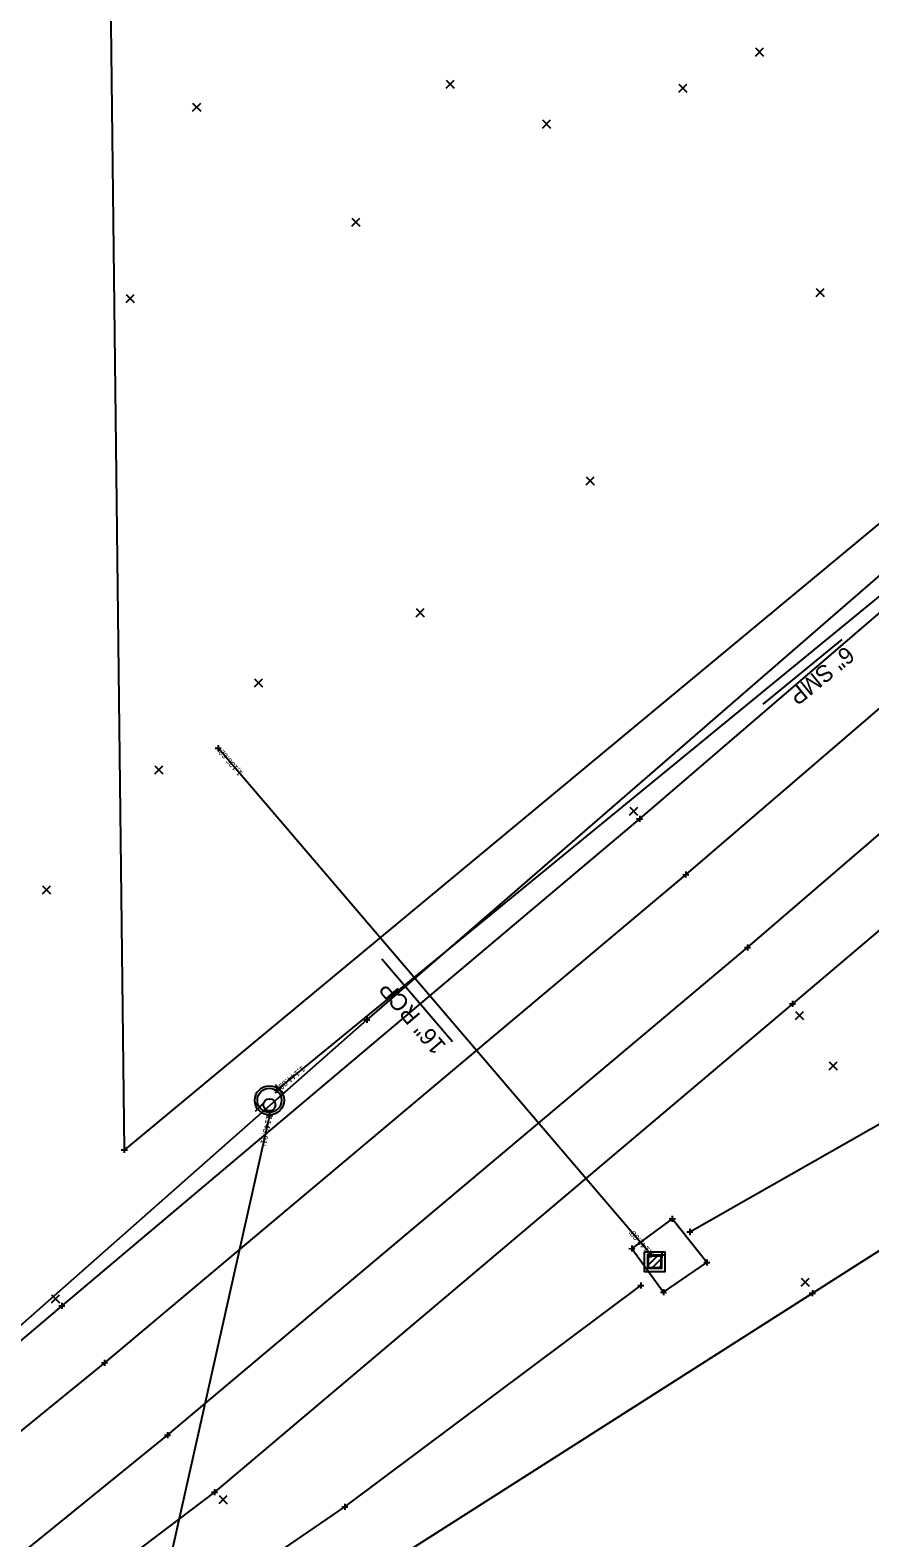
# Model space of a CAD drawing. Extents: x 142461 to 147261, y 511126 to 514697.
# Drawn here: x 145010.2 to 145149.5, y 513373.9 to 513623.9 of the extents above; entities that cross this region are included whole.
import ezdxf

# ---------------------------------------------------------------- set-up
doc = ezdxf.new("R2010")
doc.units = 0
for name, color, linetype in [('DR_X_Cells', 7, 'Continuous'), ('DR_X_Elev_Flow', 7, 'Continuous'), ('DR_X_Storm_Sewer', 7, 'Continuous'), ('DR_X_Text', 7, 'Continuous'), ('GK_Drainage_Nodes', 7, 'Continuous'), ('PM_X_Surveyed_Line', 7, 'Continuous'), ('PV_X_EOP', 7, 'Continuous'), ('RD_X_Concrete_Pad', 7, 'Continuous'), ('SC_Scratch1', 7, 'Continuous'), ('SV_X_Original_Ground', 7, 'Continuous'), ('SV_X_Random_Point', 7, 'Continuous'), ('SV_X_Shot_Marker', 7, 'Continuous'), ('SV_X_Toe_of_Slope', 7, 'Continuous'), ('SV_X_Top_of_Bank', 7, 'Continuous'), ('UT_X_Sanitary_Line', 7, 'Continuous'), ('VG_X_Tree_Line_Lt', 7, 'Continuous')]:
    doc.layers.add(name, color=color, linetype=linetype)

msp = doc.modelspace()

# ---------------------------------------------------------------- linework, layer by layer
at = {"layer": 'DR_X_Cells'}
for p, q in [((145112.65, 513419.06), (145114.41, 513420.82)), ((145112.65, 513420.19), (145113.28, 513420.82)), ((145113.25, 513418.53), (145114.94, 513420.22)), ((145114.38, 513418.53), (145114.94, 513419.09))]:
    msp.add_line(p, q, dxfattribs=at)
for points in [[(145112.13, 513421.34), (145115.46, 513421.34), (145115.46, 513418), (145112.13, 513418)], [(145112.65, 513420.82), (145114.94, 513420.82), (145114.94, 513418.53), (145112.65, 513418.53)], [(145112.8, 513420.67), (145114.8, 513420.67), (145114.8, 513418.67), (145112.8, 513418.67)]]:
    msp.add_lwpolyline(points, close=True, dxfattribs=at)
for centre, radius in [((145049.91, 513446.44), 2.42), ((145049.91, 513446.44), 2), ((145049.91, 513445.69), 1)]:
    msp.add_circle(centre, radius, dxfattribs=at)
at = {"layer": 'DR_X_Elev_Flow'}
for p, q in [((145050.66, 513448.16), (145051.66, 513448.16)), ((145051.16, 513448.66), (145051.16, 513447.66)), ((145051.16, 513448.16), (145051.16, 513448.16)), ((145049.45, 513443.91), (145050.45, 513443.91)), ((145049.95, 513444.41), (145049.95, 513443.41)), ((145049.95, 513443.91), (145049.95, 513443.91)), ((145115.01, 513421.35), (145115.01, 513420.35)), ((145114.51, 513420.85), (145115.51, 513420.85)), ((145115.01, 513420.85), (145115.01, 513420.85))]:
    msp.add_line(p, q, dxfattribs=at)
at = {"layer": 'DR_X_Storm_Sewer'}
msp.add_line((145113.14, 513420.9), (145041.41, 513504.82), dxfattribs=at)
at = {"layer": 'DR_X_Text'}
for p, q in [((145131.82, 513512.14), (145144.87, 513522.84)), ((145068.54, 513469.9), (145080.26, 513456.18))]:
    msp.add_line(p, q, dxfattribs=at)
at = {"layer": 'GK_Drainage_Nodes'}
for p, q in [((145049.91, 513448.44), (145049.91, 513448.44)), ((145049.91, 513446.44), (145049.91, 513446.44)), ((145049.91, 513446.44), (145049.91, 513446.44)), ((145049.91, 513445.69), (145049.91, 513445.69)), ((145049.91, 513444.44), (145049.91, 513444.44)), ((145113.8, 513421.34), (145113.8, 513421.34)), ((145112.8, 513419.67), (145112.8, 513419.67)), ((145113.8, 513420.67), (145113.8, 513420.67)), ((145113.8, 513419.67), (145113.8, 513419.67)), ((145113.8, 513419.67), (145113.8, 513419.67)), ((145113.8, 513419.67), (145113.8, 513419.67)), ((145114.8, 513419.67), (145114.8, 513419.67)), ((145113.8, 513418.67), (145113.8, 513418.67)), ((145113.8, 513418), (145113.8, 513418))]:
    msp.add_line(p, q, dxfattribs=at)
msp.add_circle((145049.91, 513446.44), 2, dxfattribs=at)
at = {"layer": 'PM_X_Surveyed_Line'}
for points in [[(145244.8, 513598.91), (145189.1, 513544.15), (145118.95, 513483.86), (145022.54, 513402.94), (144981.98, 513369.93), (144853.86, 513268.93), (144843.13, 513260.73), (144805.16, 513232.38), (144766.25, 513204.67), (144725.33, 513176.3), (144684.91, 513148.47), (144644.29, 513120.74), (144603.48, 513093.63), (144562.1, 513066.23), (144520.96, 513039), (144479.14, 513010.91), (144437.33, 512982.92), (144395.18, 512954.5), (144353.44, 512926.48), (144318.54, 512903.34), (144276.1, 512875.34), (144232.02, 512845.98), (144188.92, 512817.39), (144145.08, 512788.07)], [(144863.53, 513255.94), (144992.11, 513357.76), (145033.02, 513390.91), (145129.2, 513471.78), (145199.04, 513531.8), (145259.33, 513584.12)]]:
    msp.add_lwpolyline(points, dxfattribs=at)
at = {"layer": 'PV_X_EOP'}
for p, q in [((145181.78, 513553.71), (145111.31, 513493.11)), ((145111.31, 513493.11), (145015.48, 513412.35)), ((145015.48, 513412.35), (144974.38, 513377.89))]:
    msp.add_line(p, q, dxfattribs=at)
msp.add_lwpolyline([(145289.66, 513607.81), (145278.01, 513598.6), (145276.66, 513600.17), (145272.01, 513596.3), (145273.34, 513594.61), (145259.72, 513582.73), (145259.85, 513578.53), (145241.47, 513552.18), (145207.57, 513522.52), (145136.67, 513462.42), (145040.82, 513381.46), (145013.06, 513360.46), (145002.34, 513355.98), (144995.52, 513354.02), (144864.91, 513253.13), (144870.59, 513243.84), (144959.33, 513299.47), (145056.87, 513361.54), (145139.95, 513414.46), (145215.58, 513462.65), (145285.89, 513507.37)], dxfattribs=at)
at = {"layer": 'RD_X_Concrete_Pad'}
msp.add_lwpolyline([(145110.03, 513421.85), (145115.27, 513414.61), (145122.45, 513419.56), (145116.73, 513426.81)], close=True, dxfattribs=at)
at = {"layer": 'SV_X_Original_Ground'}
msp.add_lwpolyline([(144853.86, 513268.93), (144863.53, 513255.94), (144864.91, 513253.13), (144870.59, 513243.84), (144959.33, 513299.47), (145056.87, 513361.54), (145139.95, 513414.46), (145215.58, 513462.65), (145285.89, 513507.37), (145368.16, 513559.73), (145452.44, 513613.25), (145537.78, 513667.71), (145623.97, 513722.57), (145710.71, 513777.95), (145799.7, 513834.74), (145881.69, 513886.93), (145970.86, 513943.75), (146060.64, 514001.13), (146137.55, 514051.63), (146134.78, 514057.05), (146132.28, 514060.58), (146129.15, 514064.67), (146123.97, 514079.6), (146211.14, 514122.87)], dxfattribs=at)
at = {"layer": 'SV_X_Random_Point'}
for p, q in [((145130.52, 513619.58), (145131.85, 513620.92)), ((145130.52, 513620.92), (145131.85, 513619.58)), ((145079.21, 513614.26), (145080.54, 513615.59)), ((145079.21, 513615.59), (145080.54, 513614.26)), ((145117.82, 513613.57), (145119.15, 513614.9)), ((145117.82, 513614.9), (145119.15, 513613.57)), ((145037.18, 513610.42), (145038.51, 513611.76)), ((145037.18, 513611.76), (145038.51, 513610.42)), ((145095.19, 513607.65), (145096.53, 513608.98)), ((145095.19, 513608.98), (145096.53, 513607.65)), ((145063.56, 513591.36), (145064.9, 513592.7)), ((145063.56, 513592.7), (145064.9, 513591.36)), ((145026.15, 513578.73), (145027.48, 513580.07)), ((145026.15, 513580.07), (145027.48, 513578.73)), ((145140.57, 513579.7), (145141.9, 513581.04)), ((145140.57, 513581.04), (145141.9, 513579.7)), ((145102.46, 513548.5), (145103.79, 513549.83)), ((145102.46, 513549.83), (145103.79, 513548.5)), ((145074.27, 513526.62), (145075.6, 513527.96)), ((145074.27, 513527.96), (145075.6, 513526.62)), ((145047.45, 513514.99), (145048.78, 513516.32)), ((145047.45, 513516.32), (145048.78, 513514.99)), ((145030.92, 513500.57), (145032.25, 513501.91)), ((145030.92, 513501.91), (145032.25, 513500.57)), ((145109.65, 513493.73), (145111, 513495.05)), ((145109.66, 513495.06), (145110.98, 513493.71)), ((145012.28, 513480.65), (145013.61, 513481.99)), ((145012.28, 513481.99), (145013.61, 513480.65)), ((145137.15, 513459.85), (145138.5, 513461.17)), ((145137.17, 513461.18), (145138.48, 513459.83)), ((145142.74, 513451.49), (145144.07, 513452.82)), ((145142.74, 513452.82), (145144.07, 513451.49)), ((145050.87, 513447.71), (145052.22, 513449.03)), ((145050.89, 513449.05), (145052.21, 513447.7)), ((145047.59, 513444.65), (145048.94, 513445.98)), ((145047.61, 513445.99), (145048.93, 513444.64)), ((145138.07, 513415.64), (145139.42, 513416.96)), ((145138.09, 513416.98), (145139.41, 513415.63)), ((145013.76, 513412.87), (145015.11, 513414.19)), ((145013.78, 513414.21), (145015.1, 513412.86)), ((145041.55, 513379.58), (145042.9, 513380.9)), ((145041.57, 513380.91), (145042.89, 513379.56))]:
    msp.add_line(p, q, dxfattribs=at)
at = {"layer": 'SV_X_Shot_Marker'}
for p, q in [((145040.91, 513504.82), (145041.91, 513504.82)), ((145041.41, 513505.32), (145041.41, 513504.32)), ((145041.41, 513504.82), (145041.41, 513504.82)), ((145110.81, 513493.12), (145111.81, 513493.11)), ((145111.32, 513493.61), (145111.31, 513492.61)), ((145111.31, 513493.11), (145111.31, 513493.11)), ((145118.45, 513483.86), (145119.45, 513483.85)), ((145118.95, 513484.36), (145118.94, 513483.36)), ((145118.95, 513483.86), (145118.95, 513483.86)), ((145128.7, 513471.78), (145129.7, 513471.77)), ((145129.21, 513472.28), (145129.2, 513471.28)), ((145129.2, 513471.78), (145129.2, 513471.78)), ((145136.17, 513462.43), (145137.17, 513462.42)), ((145136.68, 513462.92), (145136.67, 513461.92)), ((145136.67, 513462.42), (145136.67, 513462.42)), ((145065.59, 513459.78), (145066.59, 513459.78)), ((145066.09, 513460.28), (145066.09, 513459.28)), ((145066.09, 513459.78), (145066.09, 513459.78)), ((145025.85, 513438.72), (145025.84, 513437.72)), ((145025.35, 513438.23), (145026.35, 513438.22)), ((145025.85, 513438.22), (145025.85, 513438.22)), ((145116.23, 513426.82), (145117.23, 513426.81)), ((145116.73, 513427.31), (145116.72, 513426.31)), ((145116.73, 513426.81), (145116.73, 513426.81)), ((145119.12, 513424.61), (145120.12, 513424.61)), ((145119.62, 513425.11), (145119.62, 513424.11)), ((145119.62, 513424.61), (145119.62, 513424.61)), ((145109.53, 513421.85), (145110.53, 513421.84)), ((145110.04, 513422.35), (145110.02, 513421.35)), ((145110.03, 513421.85), (145110.03, 513421.85)), ((145113.14, 513421.4), (145113.14, 513420.4)), ((145112.64, 513420.9), (145113.64, 513420.9)), ((145113.14, 513420.9), (145113.14, 513420.9)), ((145121.95, 513419.57), (145122.95, 513419.56)), ((145122.46, 513420.06), (145122.45, 513419.06)), ((145122.45, 513419.56), (145122.45, 513419.56)), ((145111.52, 513416.25), (145111.52, 513415.25)), ((145111.02, 513415.75), (145112.02, 513415.75)), ((145111.52, 513415.75), (145111.52, 513415.75)), ((145114.77, 513414.61), (145115.77, 513414.6)), ((145115.27, 513415.11), (145115.26, 513414.11)), ((145115.27, 513414.61), (145115.27, 513414.61)), ((145139.45, 513414.47), (145140.45, 513414.45)), ((145139.95, 513414.96), (145139.94, 513413.96)), ((145139.95, 513414.46), (145139.95, 513414.46)), ((145014.98, 513412.36), (145015.98, 513412.35)), ((145015.49, 513412.85), (145015.48, 513411.85)), ((145015.48, 513412.35), (145015.48, 513412.35)), ((145022.04, 513402.95), (145023.04, 513402.94)), ((145022.55, 513403.44), (145022.54, 513402.44)), ((145022.54, 513402.94), (145022.54, 513402.94)), ((145033.03, 513391.41), (145033.02, 513390.41)), ((145032.52, 513390.91), (145033.52, 513390.9)), ((145033.02, 513390.91), (145033.02, 513390.91)), ((145040.32, 513381.46), (145041.32, 513381.45)), ((145040.83, 513381.96), (145040.82, 513380.96)), ((145040.82, 513381.46), (145040.82, 513381.46)), ((145061.92, 513379.03), (145062.92, 513379.03)), ((145062.42, 513379.53), (145062.42, 513378.53)), ((145062.42, 513379.03), (145062.42, 513379.03))]:
    msp.add_line(p, q, dxfattribs=at)
at = {"layer": 'SV_X_Toe_of_Slope'}
for points in [[(145119.62, 513424.61), (145173.27, 513455.16), (145224.92, 513488.67), (145276.97, 513521.4), (145328.93, 513556.92), (145380.26, 513589.74), (145431.18, 513623.07), (145480.29, 513655.45), (145533.69, 513687.8), (145582.02, 513724.74), (145628.84, 513766.74), (145660.19, 513809.96), (145712.81, 513840.49)], [(144902.12, 513271.86), (144957.85, 513307.93), (145007.68, 513341.58), (145062.42, 513379.03), (145111.52, 513415.75)]]:
    msp.add_lwpolyline(points, dxfattribs=at)
at = {"layer": 'SV_X_Top_of_Bank'}
msp.add_lwpolyline([(145216.9, 513602.26), (145198.94, 513574.98), (145066.09, 513459.78), (144977.8, 513381.92), (144941.22, 513354.92), (144938.7, 513352.73)], dxfattribs=at)
at = {"layer": 'UT_X_Sanitary_Line'}
for p, q in [((145226.53, 513591.91), (145051.16, 513448.16)), ((145049.95, 513443.91), (144977.14, 513120))]:
    msp.add_line(p, q, dxfattribs=at)
at = {"layer": 'VG_X_Tree_Line_Lt'}
msp.add_lwpolyline([(145193.73, 513634.84), (145192.23, 513576.23), (145025.85, 513438.22), (145019.15, 514007.47)], dxfattribs=at)

# ---------------------------------------------------------------- texts
at = {"layer": 'DR_X_Text'}
for s, rotation, p in [('6" SMP', 219.3426, (145145.48, 513521.91)), ('16" RCP', 130.5217, (145079.35, 513455.55))]:
    msp.add_text(s, height=2.8, rotation=rotation, dxfattribs=at).set_placement(p)
at = {"layer": 'SC_Scratch1'}
for s, rotation, p in [("1,136.62'", 130.5217, (145045.54, 513500.75)), ("1,144.03'", 219.3426, (145055.32, 513452.21)), ("1143.91'", 257.333, (145049.46, 513444.02)), ("1142.08'", 130.5217, (145113.52, 513421.22))]:
    msp.add_text(s, height=1, rotation=rotation, dxfattribs=at).set_placement(p)

doc.saveas('drawing.dxf')
